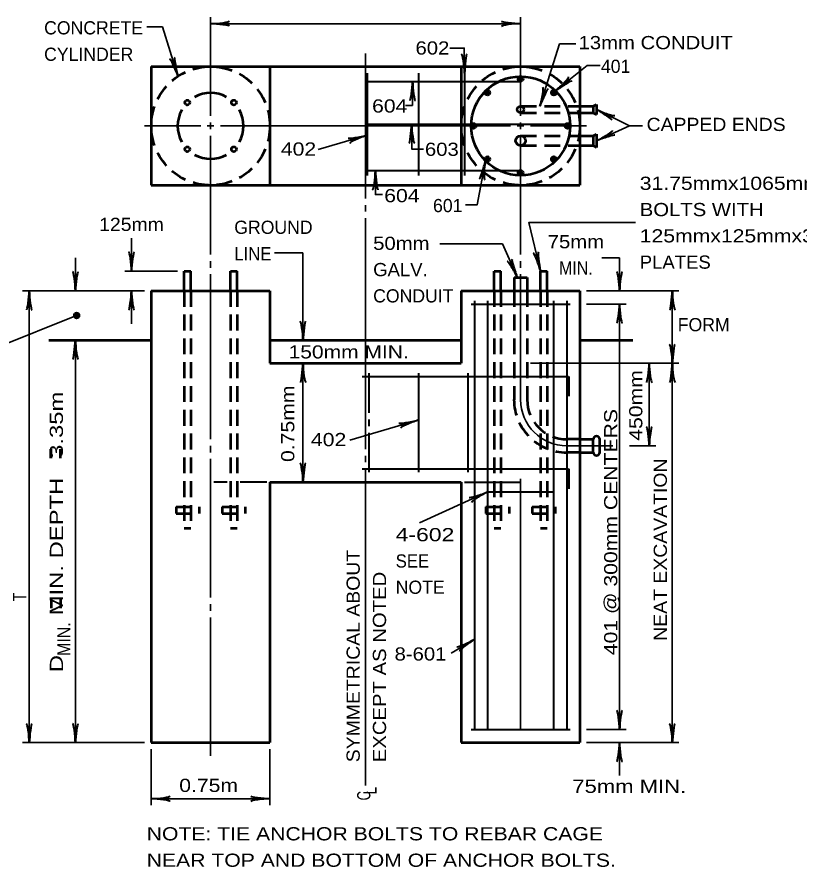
# Model space of a CAD drawing. Extents: x -29 to 827, y -14 to 530.
# Drawn here: x 196.8 to 340.2, y 180.4 to 336.3 of the extents above; entities that cross this region are included whole.
import ezdxf
from ezdxf.enums import TextEntityAlignment as Align

# ---------------------------------------------------------------- set-up
doc = ezdxf.new("R2010")
doc.units = 0
doc.header["$LTSCALE"] = 0.97
doc.linetypes.add('MEDIUM_DASHED', pattern=[4.5, 3, -1.5])
doc.layers.add('1', color=7, linetype='Continuous', lineweight=53)

msp = doc.modelspace()

# ---------------------------------------------------------------- hatches: boundary and pattern name
at = {"layer": '1'}
for points in [[(289.6196, 324.9621, 1), (288.7124, 324.9621, 1)], [(283.5254, 322.4377, 1), (282.6182, 322.4377, 1)], [(295.7138, 322.4378, 1), (294.8066, 322.4378, 1)], [(281.0012, 316.3437, 1), (280.094, 316.3437, 1)], [(298.238, 316.3437, 1), (297.3308, 316.3437, 1)], [(283.5253, 310.2494, 1), (282.6181, 310.2494, 1)], [(295.7139, 310.2496, 1), (294.8067, 310.2496, 1)], [(289.6196, 307.7253, 1), (288.7124, 307.7253, 1)], [(208.2861, 281.5657, 1), (207.1982, 281.5657, 1)]]:
    msp.add_hatch(color=256, dxfattribs=at).paths.add_polyline_path(points)

# ---------------------------------------------------------------- linework, layer by layer
at = {"layer": '1', "lineweight": 35}
for p, q in [((232.3076, 335.0878), (289.1636, 335.0878)), ((260.7476, 329.6398), (260.7476, 303.0478)), ((269.3636, 324.4798), (269.3636, 320.1118)), ((269.3636, 320.1118), (268.0676, 320.1118)), ((232.3076, 316.9438), (232.3076, 315.7438)), ((289.1636, 316.9438), (289.1636, 315.7438)), ((231.7076, 316.3438), (232.9076, 316.3438)), ((234.1316, 316.3438), (238.3556, 316.3438)), ((288.5636, 316.3438), (289.7636, 316.3438)), ((309.1316, 316.3438), (311.5316, 316.3438)), ((252.0116, 311.9998), (261.0356, 314.6158)), ((260.7476, 301.8238), (260.7476, 300.6238)), ((260.7476, 299.3998), (260.7476, 257.0638)), ((217.7876, 289.7278), (217.7876, 295.7758)), ((244.0436, 293.0638), (249.2516, 293.0638)), ((249.2516, 277.0318), (249.2516, 293.0638)), ((207.5156, 286.1038), (207.5156, 292.1518)), ((232.3076, 291.5518), (232.3076, 290.3278)), ((289.1636, 291.5518), (289.1636, 290.3278)), ((307.3076, 292.1518), (304.0436, 292.1518)), ((307.3076, 286.1038), (307.3076, 292.1518)), ((226.2596, 289.7278), (216.5876, 289.7278)), ((232.3076, 289.1278), (232.3076, 258.8878)), ((289.1636, 289.1278), (289.1636, 266.1358)), ((220.2116, 286.1038), (197.8436, 286.1038)), ((199.0436, 286.1038), (199.0436, 203.2558)), ((217.7876, 286.1038), (217.7876, 280.0558)), ((301.2596, 286.1038), (318.2036, 286.1038)), ((301.2596, 283.6798), (308.5076, 283.6798)), ((307.3076, 283.6798), (307.3076, 205.6558)), ((207.7316, 281.5678), (190.0196, 274.4878)), ((207.5156, 277.0318), (207.5156, 203.2558)), ((249.2516, 272.8078), (249.2516, 251.0158)), ((290.9876, 272.8078), (318.2036, 272.8078)), ((312.7556, 257.6878), (312.7556, 272.8078)), ((257.8196, 258.7198), (270.3236, 262.3678)), ((232.3076, 257.6878), (232.3076, 256.4638)), ((297.6356, 257.6878), (300.0596, 257.6878)), ((300.0596, 257.6878), (306.1076, 257.6878)), ((309.1316, 257.6878), (313.9556, 257.6878)), ((260.7476, 255.8638), (260.7476, 254.6638)), ((232.3076, 255.2638), (232.3076, 229.8478)), ((260.7476, 253.4398), (260.7476, 195.3838)), ((289.1636, 251.6398), (289.1636, 205.6558)), ((283.1156, 249.2158), (270.6184, 243.5634)), ((232.3076, 228.6478), (232.3076, 227.4478)), ((232.3076, 226.2238), (232.3076, 200.8318)), ((280.6916, 222.1918), (276.4196, 219.6478)), ((301.2596, 205.6558), (308.5076, 205.6558)), ((220.2116, 203.2558), (197.8436, 203.2558)), ((301.2596, 203.2558), (318.2036, 203.2558)), ((307.3076, 203.2558), (307.3076, 197.2078)), ((221.4356, 202.0318), (221.4356, 191.7598)), ((243.2036, 202.0318), (243.2036, 191.7598)), ((221.4356, 192.9598), (243.2036, 192.9598))]:
    msp.add_line(p, q, dxfattribs=at)
at = {"layer": '1'}
for p, q in [((221.4356, 327.2398), (300.0596, 327.2398)), ((221.4356, 327.2398), (221.4356, 305.4478)), ((243.2036, 327.2398), (243.2036, 305.4478)), ((278.2676, 327.2398), (278.2676, 305.4478)), ((300.0596, 327.2398), (300.0596, 305.4478)), ((300.0596, 319.9678), (302.4596, 319.9678)), ((302.4596, 319.9678), (303.0836, 320.2798)), ((302.4596, 319.9678), (302.4596, 318.7678)), ((303.0836, 320.2798), (303.0836, 318.4558)), ((300.0596, 318.7678), (302.4596, 318.7678)), ((302.4596, 318.7678), (303.0836, 318.4558)), ((300.0596, 314.5198), (302.4596, 314.5198)), ((302.4596, 314.5198), (303.0836, 314.8318)), ((302.4596, 314.5198), (302.4596, 312.7198)), ((303.0836, 314.8318), (303.0836, 312.4078)), ((300.0596, 312.7198), (302.4596, 312.7198)), ((302.4596, 312.7198), (303.0836, 312.4078)), ((221.4356, 305.4478), (300.0596, 305.4478)), ((227.4836, 286.1038), (227.4836, 289.7278)), ((227.4836, 289.7278), (228.6836, 289.7278)), ((228.6836, 286.1038), (228.6836, 289.7278)), ((235.9316, 286.1038), (235.9316, 289.7278)), ((235.9316, 289.7278), (237.1556, 289.7278)), ((237.1556, 286.1038), (237.1556, 289.7278)), ((284.3156, 286.1038), (284.3156, 289.7278)), ((284.3156, 289.7278), (285.5396, 289.7278)), ((285.5396, 286.1038), (285.5396, 289.7278)), ((287.9636, 288.5278), (290.3636, 288.5278)), ((287.9636, 288.5278), (287.9636, 286.1038)), ((290.3636, 288.5278), (290.3636, 286.1038)), ((292.7876, 286.1038), (292.7876, 289.7278)), ((292.7876, 289.7278), (294.0116, 289.7278)), ((294.0116, 286.1038), (294.0116, 289.7278)), ((221.4356, 286.1038), (221.4356, 203.2558)), ((221.4356, 286.1038), (243.2036, 286.1038)), ((243.2036, 286.1038), (243.2036, 272.8078)), ((278.2676, 286.1038), (300.0596, 286.1038)), ((278.2676, 286.1038), (278.2676, 272.8078)), ((300.0596, 286.1038), (300.0596, 203.2558)), ((202.6676, 277.0318), (221.4356, 277.0318)), ((243.2036, 277.0318), (278.2676, 277.0318)), ((300.0596, 277.0318), (309.7316, 277.0318)), ((243.2036, 272.8078), (278.2676, 272.8078)), ((300.0596, 258.8878), (302.4596, 258.8878)), ((302.4596, 256.4638), (302.4596, 258.8878)), ((303.6836, 256.4638), (303.6836, 258.8878)), ((300.0596, 256.4638), (302.4596, 256.4638)), ((243.2036, 251.0158), (278.2676, 251.0158)), ((243.2036, 251.0158), (243.2036, 203.2558)), ((278.2676, 251.0158), (278.2676, 203.2558)), ((221.4356, 203.2558), (243.2036, 203.2558)), ((278.2676, 203.2558), (300.0596, 203.2558))]:
    msp.add_line(p, q, dxfattribs=at)
at = {"layer": '1', "lineweight": 40}
for p, q in [((261.0356, 326.0158), (261.0356, 307.2718)), ((270.4196, 326.0158), (270.4196, 307.2718)), ((278.8916, 326.0158), (278.8916, 307.2718)), ((261.0356, 324.5038), (289.1636, 324.5038)), ((261.0356, 316.6558), (298.2356, 316.6558)), ((261.0356, 308.1838), (289.1636, 308.1838)), ((280.0916, 283.6798), (298.2356, 283.6798)), ((280.6916, 284.2798), (280.6916, 205.6558)), ((283.1156, 284.2798), (283.1156, 205.6558)), ((295.2116, 284.2798), (295.2116, 205.6558)), ((297.6356, 284.2798), (297.6356, 205.6558)), ((260.1236, 270.3838), (297.9236, 270.3838)), ((261.3476, 270.9838), (261.3476, 263.7358)), ((270.4196, 270.9838), (270.4196, 252.8398)), ((279.4916, 270.9838), (279.4916, 252.8398)), ((261.3476, 262.5118), (261.3476, 261.3118)), ((261.3476, 260.0878), (261.3476, 252.8398)), ((260.1236, 253.4398), (297.9236, 253.4398)), ((235.3316, 251.0158), (232.9076, 251.0158)), ((242.6036, 251.0158), (237.7556, 251.0158)), ((278.8916, 251.0158), (289.1636, 251.0158)), ((283.1156, 249.2158), (295.2116, 249.2158)), ((280.0916, 205.6558), (298.2356, 205.6558))]:
    msp.add_line(p, q, dxfattribs=at)
at = {"layer": '1', "linetype": 'MEDIUM_DASHED'}
for p, q in [((289.1636, 319.9678), (300.0596, 319.9678)), ((289.1636, 318.7678), (300.0596, 318.7678)), ((289.1636, 314.5198), (300.0596, 314.5198)), ((289.1636, 312.7198), (300.0596, 312.7198)), ((227.4836, 286.1038), (227.4836, 242.5678)), ((228.6836, 286.1038), (228.6836, 242.5678)), ((235.9316, 286.1038), (235.9316, 242.5678)), ((237.1556, 286.1038), (237.1556, 242.5678)), ((284.3156, 286.1038), (284.3156, 242.5678)), ((285.5396, 286.1038), (285.5396, 242.5678)), ((287.9636, 286.1038), (287.9636, 266.1358)), ((290.3636, 286.1038), (290.3636, 266.1358)), ((292.7876, 286.1038), (292.7876, 242.5678)), ((294.0116, 286.1038), (294.0116, 242.5678)), ((300.0596, 258.8878), (297.6356, 258.8878)), ((300.0596, 256.4638), (297.6356, 256.4638)), ((225.9716, 246.4798), (230.1956, 246.4798)), ((225.9716, 246.4798), (225.9716, 245.2798)), ((230.1956, 246.4798), (230.1956, 245.2798)), ((234.4196, 246.4798), (238.6676, 246.4798)), ((234.4196, 246.4798), (234.4196, 245.2798)), ((238.6676, 246.4798), (238.6676, 245.2798)), ((282.8036, 246.4798), (287.0516, 246.4798)), ((282.8036, 246.4798), (282.8036, 245.2798)), ((287.0516, 246.4798), (287.0516, 245.2798)), ((291.2756, 246.4798), (295.5236, 246.4798)), ((291.2756, 246.4798), (291.2756, 245.2798)), ((295.5236, 246.4798), (295.5236, 245.2798)), ((225.9716, 245.2798), (230.1956, 245.2798)), ((234.4196, 245.2798), (238.6676, 245.2798)), ((282.8036, 245.2798), (287.0516, 245.2798)), ((291.2756, 245.2798), (295.5236, 245.2798)), ((227.4836, 242.5678), (228.6836, 242.5678)), ((235.9316, 242.5678), (237.1556, 242.5678)), ((284.3156, 242.5678), (285.5396, 242.5678)), ((292.7876, 242.5678), (294.0116, 242.5678))]:
    msp.add_line(p, q, dxfattribs=at)
at = {"layer": '1', "lineweight": 60}
for p, q in [((297.9236, 270.3838), (297.9236, 266.7598)), ((297.9236, 253.4398), (297.9236, 249.8158))]:
    msp.add_line(p, q, dxfattribs=at)
at = {"layer": '1', "lineweight": 35}
for points in [[(232.3076, 318.1678), (232.3076, 322.3918), (232.3076, 336.3118)], [(289.1636, 318.1678), (289.1636, 325.4158), (289.1636, 336.3118)], [(226.3316, 325.4398), (223.4756, 334.4878), (220.6196, 334.4878)], [(278.8916, 326.0158), (278.8436, 330.5998), (276.1796, 330.5998)], [(292.7156, 319.9678), (296.3156, 331.3678), (299.2676, 331.3678)], [(295.5716, 322.7758), (301.4036, 327.4318), (303.7556, 327.4318)], [(303.0836, 319.3678), (309.1316, 316.3438), (303.0836, 313.6318)], [(269.1956, 316.6558), (269.1956, 312.0958), (271.3316, 312.0958)], [(230.5076, 316.3438), (226.2596, 316.3438), (220.2116, 316.3438)], [(238.3556, 316.3438), (280.0916, 316.3438), (287.3396, 316.3438)], [(290.9876, 316.3438), (298.2356, 316.3438), (301.2596, 316.3438)], [(232.3076, 314.5198), (232.3076, 310.2958), (232.3076, 292.7518)], [(289.1636, 314.5198), (289.1636, 307.2718), (289.1636, 292.7518)], [(282.7076, 309.9598), (281.2196, 301.8958), (279.0356, 301.8958)], [(262.5476, 308.1118), (262.5476, 303.7438), (263.8196, 303.7438)], [(292.7876, 289.7278), (290.6516, 298.6078), (310.2563, 298.6078)], [(288.5876, 288.5278), (285.8183, 294.7246), (274.3769, 294.7246)], [(316.9796, 286.1038), (316.9796, 272.8078), (316.9796, 203.2558)]]:
    msp.add_lwpolyline(points, dxfattribs=at)
at = {"layer": '1', "linetype": 'MEDIUM_DASHED'}
for centre in [(232.3148, 316.3437), (289.166, 316.3437)]:
    msp.add_circle(centre, 10.8864, dxfattribs=at)
at = {"layer": '1'}
for centre, radius in [((289.166, 316.3437), 9.072), ((289.166, 324.9621), 0.4536), ((283.0718, 322.4377), 0.4536), ((295.2602, 322.4378), 0.4536), ((228.0383, 320.6202), 0.4536), ((236.5913, 320.6202), 0.4536), ((289.166, 319.3677), 0.6048), ((280.5476, 316.3437), 0.4536), ((297.7844, 316.3437), 0.4536), ((289.166, 313.6221), 0.9072), ((228.0383, 312.0671), 0.4536), ((236.5913, 312.0671), 0.4536), ((283.0717, 310.2494), 0.4536), ((295.2603, 310.2496), 0.4536), ((289.166, 307.7253), 0.4536)]:
    msp.add_circle(centre, radius, dxfattribs=at)
at = {"layer": '1', "lineweight": 35}
msp.add_circle((207.7422, 281.5657), 0.5439, dxfattribs=at)
at = {"layer": '1'}
for centre, radius, start, end in [((232.3148, 316.3437), 6.048, 60.95954, 119.04116), ((232.3148, 316.3437), 6.048, 150.96024, 209.04046), ((232.3148, 316.3437), 6.048, 330.95884, 29.04046), ((232.3148, 316.3437), 6.048, 240.95954, 299.03976), ((303.0764, 258.8514), 0.6059, 3.43671, 176.56329), ((303.0764, 256.5048), 0.6059, 183.43671, 356.56329)]:
    msp.add_arc(centre, radius, start, end, dxfattribs=at)
at = {"layer": '1', "linetype": 'MEDIUM_DASHED'}
for radius in [9.6768, 7.2576]:
    msp.add_arc((297.6332, 266.1453), radius, 180, 270, dxfattribs=at)
at = {"layer": '1', "lineweight": 35}
msp.add_arc((297.6332, 266.1453), 8.4672, 180, 270, dxfattribs=at)
at = {"layer": '1', "lineweight": 40}
for centre, major_axis, ratio, start_param, end_param in [((233.6347, 335.4267), (-2.16, -0.1889), 0.122415, 0.89635335, 3.14159265), ((233.6347, 335.4267), (-2.16, -0.1889), 0.122415, 0.89635335, 3.14159265), ((287.8106, 335.3484), (2.1246, -0.2125), 0.07063, 3.14071475, 5.41810995), ((233.6702, 334.8365), (-2.1246, 0.2125), 0.07063, 3.14071475, 5.41810995), ((233.6702, 334.8365), (-2.1246, 0.2125), 0.07063, 3.14071475, 5.41810995), ((287.8461, 334.7583), (2.16, 0.1889), 0.122415, 0.89635335, 3.14159265), ((226.1648, 326.8051), (0.4341, -2.0906), 0.07063, 3.14071475, 5.41810995), ((278.5356, 327.3366), (0.2127, -2.1578), 0.122415, 0.89635335, 3.14159265), ((279.1253, 327.3786), (-0.189, -2.1268), 0.07063, 3.14071475, 5.41810995), ((225.6124, 326.5944), (0.8276, -2.0041), 0.122415, 0.89635335, 3.14159265), ((269.1022, 323.1255), (0.2125, 2.1246), 0.07063, 3.14071475, 5.41810995), ((269.6924, 323.1609), (-0.1889, 2.16), 0.122415, 0.89635335, 3.14159265), ((296.3888, 323.8583), (-1.57, -1.4954), 0.122415, 0.89635335, 3.14159265), ((296.7847, 323.4192), (1.7928, 1.1597), 0.07063, 6.28230741, 8.55970261), ((292.7964, 321.3318), (-0.4694, -2.1168), 0.122415, 0.89635335, 3.14159265), ((293.3699, 321.1881), (0.8415, 1.9624), 0.07063, 6.28230741, 8.55970261), ((304.1742, 318.5326), (-1.8053, 1.1402), 0.07063, 3.14071475, 5.41810995), ((304.1742, 318.5326), (-1.8053, 1.1402), 0.07063, 3.14071475, 5.41810995), ((304.4064, 319.0763), (-2.0164, 0.797), 0.122415, 0.89635335, 3.14159265), ((304.4064, 319.0763), (-2.0164, 0.797), 0.122415, 0.89635335, 3.14159265), ((268.9407, 315.2907), (0.2125, 2.1246), 0.07063, 3.14071475, 5.41810995), ((269.5308, 315.3262), (-0.1889, 2.16), 0.122415, 0.89635335, 3.14159265), ((304.1429, 314.4685), (-1.8922, -1.0586), 0.122415, 0.89635335, 3.14159265), ((259.6698, 314.486), (-2.0996, -0.3885), 0.07063, 6.28230741, 8.55970261), ((259.8685, 313.9291), (2.0216, 0.7838), 0.122415, 0.89635335, 3.14159265), ((304.4174, 313.9449), (-2.0247, -0.6781), 0.07063, 3.14071475, 5.41810995), ((282.2179, 308.6774), (-0.5967, -2.0501), 0.07063, 6.28230741, 8.55970261), ((282.8046, 308.6045), (0.2086, 2.1582), 0.122415, 0.89635335, 3.14159265), ((262.2019, 306.7823), (0.1889, 2.16), 0.122415, 3.14159265, 5.38683196), ((262.7921, 306.7468), (-0.2125, 2.1246), 0.07063, 0.86507535, 3.14247055), ((217.4654, 291.0524), (0.1889, -2.16), 0.122415, 0.89635335, 3.14159265), ((218.0555, 291.0878), (-0.2125, -2.1246), 0.07063, 3.14071475, 5.41810995), ((292.7247, 291.11), (0.2933, -2.115), 0.07063, 3.14071475, 5.41810995), ((287.7374, 289.5923), (1.052, -1.8959), 0.122415, 0.89635335, 3.14159265), ((288.262, 289.865), (0.671, -2.027), 0.07063, 3.14071475, 5.41810995), ((292.1594, 290.9367), (0.6917, -2.0549), 0.122415, 0.89635335, 3.14159265), ((207.1838, 287.4236), (0.1889, -2.16), 0.122415, 0.89635335, 3.14159265), ((207.7739, 287.459), (-0.2125, -2.1246), 0.07063, 3.14071475, 5.41810995), ((306.9758, 287.4236), (0.1889, -2.16), 0.122415, 0.89635335, 3.14159265), ((307.5659, 287.459), (-0.2125, -2.1246), 0.07063, 3.14071475, 5.41810995), ((198.7948, 284.7483), (0.2125, 2.1246), 0.07063, 3.14071475, 5.41810995), ((198.7948, 284.7483), (0.2125, 2.1246), 0.07063, 3.14071475, 5.41810995), ((199.385, 284.7838), (-0.1889, 2.16), 0.122415, 0.89635335, 3.14159265), ((199.385, 284.7838), (-0.1889, 2.16), 0.122415, 0.89635335, 3.14159265), ((217.5436, 284.7483), (0.2125, 2.1246), 0.07063, 3.14071475, 5.41810995), ((218.1338, 284.7838), (-0.1889, 2.16), 0.122415, 0.89635335, 3.14159265), ((316.7308, 284.7483), (0.2125, 2.1246), 0.07063, 3.14071475, 5.41810995), ((316.7308, 284.7483), (0.2125, 2.1246), 0.07063, 3.14071475, 5.41810995), ((317.321, 284.7838), (-0.1889, 2.16), 0.122415, 0.89635335, 3.14159265), ((317.321, 284.7838), (-0.1889, 2.16), 0.122415, 0.89635335, 3.14159265), ((307.054, 282.3291), (0.2125, 2.1246), 0.07063, 3.14071475, 5.41810995), ((307.6442, 282.3646), (-0.1889, 2.16), 0.122415, 0.89635335, 3.14159265), ((248.915, 278.3516), (0.1889, -2.16), 0.122415, 0.89635335, 3.14159265), ((249.5051, 278.387), (-0.2125, -2.1246), 0.07063, 3.14071475, 5.41810995), ((207.262, 275.6763), (0.2125, 2.1246), 0.07063, 3.14071475, 5.41810995), ((207.8522, 275.7118), (-0.1889, 2.16), 0.122415, 0.89635335, 3.14159265), ((316.6526, 274.118), (0.1889, -2.16), 0.122415, 0.89635335, 3.14159265), ((316.6526, 274.118), (0.1889, -2.16), 0.122415, 0.89635335, 3.14159265), ((317.2427, 274.1534), (-0.2125, -2.1246), 0.07063, 3.14071475, 5.41810995), ((317.2427, 274.1534), (-0.2125, -2.1246), 0.07063, 3.14071475, 5.41810995), ((248.9932, 271.4427), (0.2125, 2.1246), 0.07063, 3.14071475, 5.41810995), ((248.9932, 271.4427), (0.2125, 2.1246), 0.07063, 3.14071475, 5.41810995), ((249.5834, 271.4782), (-0.1889, 2.16), 0.122415, 0.89635335, 3.14159265), ((249.5834, 271.4782), (-0.1889, 2.16), 0.122415, 0.89635335, 3.14159265), ((312.4972, 271.4427), (0.2125, 2.1246), 0.07063, 3.14071475, 5.41810995), ((312.4972, 271.4427), (0.2125, 2.1246), 0.07063, 3.14071475, 5.41810995), ((313.0874, 271.4782), (-0.1889, 2.16), 0.122415, 0.89635335, 3.14159265), ((313.0874, 271.4782), (-0.1889, 2.16), 0.122415, 0.89635335, 3.14159265), ((316.7308, 271.4427), (0.2125, 2.1246), 0.07063, 3.14071475, 5.41810995), ((316.7308, 271.4427), (0.2125, 2.1246), 0.07063, 3.14071475, 5.41810995), ((317.321, 271.4782), (-0.1889, 2.16), 0.122415, 0.89635335, 3.14159265), ((317.321, 271.4782), (-0.1889, 2.16), 0.122415, 0.89635335, 3.14159265), ((268.9571, 262.2283), (-2.0996, -0.3885), 0.07063, 6.28230741, 8.55970261), ((269.1558, 261.6715), (2.0216, 0.7838), 0.122415, 0.89635335, 3.14159265), ((312.419, 258.998), (0.1889, -2.16), 0.122415, 0.89635335, 3.14159265), ((312.419, 258.998), (0.1889, -2.16), 0.122415, 0.89635335, 3.14159265), ((313.0091, 259.0334), (-0.2125, -2.1246), 0.07063, 3.14071475, 5.41810995), ((313.0091, 259.0334), (-0.2125, -2.1246), 0.07063, 3.14071475, 5.41810995), ((248.915, 252.3452), (0.1889, -2.16), 0.122415, 0.89635335, 3.14159265), ((249.5051, 252.3806), (-0.2125, -2.1246), 0.07063, 3.14071475, 5.41810995), ((281.7775, 248.8858), (-2.0235, -0.6816), 0.07063, 6.28230741, 8.55970261), ((282.0529, 248.3626), (1.8904, 1.0619), 0.122415, 0.89635335, 3.14159265), ((279.402, 221.7119), (1.9367, 0.8991), 0.07063, 3.14071475, 5.41810995), ((279.7331, 221.2221), (1.7627, 1.2625), 0.122415, 0.89635335, 3.14159265), ((306.9758, 206.9852), (0.1889, -2.16), 0.122415, 0.89635335, 3.14159265), ((306.9758, 206.9852), (0.1889, -2.16), 0.122415, 0.89635335, 3.14159265), ((307.5659, 207.0206), (-0.2125, -2.1246), 0.07063, 3.14071475, 5.41810995), ((307.5659, 207.0206), (-0.2125, -2.1246), 0.07063, 3.14071475, 5.41810995), ((198.7166, 204.566), (0.1889, -2.16), 0.122415, 0.89635335, 3.14159265), ((199.3067, 204.6014), (-0.2125, -2.1246), 0.07063, 3.14071475, 5.41810995), ((207.1838, 204.566), (0.1889, -2.16), 0.122415, 0.89635335, 3.14159265), ((207.7739, 204.6014), (-0.2125, -2.1246), 0.07063, 3.14071475, 5.41810995), ((316.6526, 204.566), (0.1889, -2.16), 0.122415, 0.89635335, 3.14159265), ((316.6526, 204.566), (0.1889, -2.16), 0.122415, 0.89635335, 3.14159265), ((317.2427, 204.6014), (-0.2125, -2.1246), 0.07063, 3.14071475, 5.41810995), ((317.2427, 204.6014), (-0.2125, -2.1246), 0.07063, 3.14071475, 5.41810995), ((307.054, 201.8907), (0.2125, 2.1246), 0.07063, 3.14071475, 5.41810995), ((307.6442, 201.9262), (-0.1889, 2.16), 0.122415, 0.89635335, 3.14159265), ((222.7483, 193.2987), (-2.16, -0.1889), 0.122415, 0.89635335, 3.14159265), ((222.7483, 193.2987), (-2.16, -0.1889), 0.122415, 0.89635335, 3.14159265), ((241.8458, 193.2204), (2.1246, -0.2125), 0.07063, 3.14071475, 5.41810995), ((222.7838, 192.7085), (-2.1246, 0.2125), 0.07063, 3.14071475, 5.41810995), ((222.7838, 192.7085), (-2.1246, 0.2125), 0.07063, 3.14071475, 5.41810995), ((241.8813, 192.6303), (2.16, 0.1889), 0.122415, 0.89635335, 3.14159265)]:
    msp.add_ellipse(centre, major_axis=major_axis, ratio=ratio, start_param=start_param, end_param=end_param, dxfattribs=at)

# ---------------------------------------------------------------- texts
at = {"layer": '1'}
for s, p in [('CONCRETE', (201.7796, 333.1198)), ('CYLINDER', (201.7796, 328.2718)), ('401', (303.8996, 326.0638)), ('601', (273.1076, 300.5278)), ('GROUND', (236.6516, 296.5438)), ('CONDUIT', (262.1262, 283.9678)), ('FORM', (317.9876, 278.6878)), ('NOTE', (266.2568, 230.5393))]:
    msp.add_text(s, height=2.419, dxfattribs=at).set_placement(p)
for s, height, width, p in [('13mm CONDUIT', 2.419, 1.15, (299.7956, 330.4078)), ('602', 2.419, 1.15, (269.8916, 329.4238)), ('604', 2.419, 1.2, (261.9236, 318.7918)), ('CAPPED ENDS', 2.419, 1.1, (312.2756, 315.4078)), ('402', 2.419, 1.2, (245.1956, 310.8958)), ('603', 2.419, 1.15, (271.6196, 310.8478)), ('31.75mmx1065mm ANCHOR', 2.419, 1.2, (311.0187, 304.6126)), ('604', 2.419, 1.2, (264.1556, 302.3518)), ('BOLTS WITH', 2.419, 1.15, (311.0187, 299.7934)), ('125mm', 2.419, 1.1, (211.8705, 297.0766)), ('125mmx125mmx38mm BOTTOM', 2.419, 1.2, (311.0187, 294.9742)), ('50mm', 2.419, 1.15, (262.1262, 293.6062)), ('LINE', 2.419, 0.95, (236.6516, 291.6958)), ('PLATES', 2.419, 1.05, (311.0187, 290.155)), ('GALV.', 2.419, 1.05, (262.1262, 288.787)), ('150mm MIN.', 2.4, 1.2, (246.6143, 273.6995)), ('402', 2.419, 1.2, (250.7156, 257.6158)), ('4-602', 2.419, 1.3, (266.2568, 240.1777)), ('SEE', 2.419, 0.95, (266.2568, 235.3585)), ('8-601', 2.419, 1.15, (266.0516, 218.3038)), ('0.75m', 2.419, 1.2, (226.5576, 194.2078)), ('75mm MIN.', 2.419, 1.25, (298.6492, 194.035)), ('NOTE: TIE ANCHOR BOLTS TO REBAR CAGE', 2.419, 1.2, (220.5903, 185.3295)), ('NEAR TOP AND BOTTOM OF ANCHOR BOLTS.', 2.419, 1.2, (220.5903, 180.4815))]:
    msp.add_text(s, height=height, dxfattribs=dict(at, width=width)).set_placement(p)
for s, width, p in [('75mm', 1.15, (299.3094, 293.9038)), ('MIN.', 0.9, (299.3094, 289.0846))]:
    msp.add_text(s, height=2.419, dxfattribs=dict(at, width=width)).set_placement(p, align=Align.CENTER)
for s, height, width, p in [('450mm', 2.419, 1.2, (311.4985, 258.6098)), ('0.75mm', 2.419, 1.2, (247.6697, 254.7122)), ('D      MIN. DEPTH   3.35m', 2.419, 1.35, (205.2356, 216.1678)), ('401 @ 300mm CENTERS', 2.419, 1.2, (306.9043, 219.2878)), ('=', 4.8, 0.55, (206.1758, 255.237)), ('NEAT EXCAVATION', 2.419, 1.1, (315.9956, 221.9278)), ('SYMMETRICAL ABOUT', 2.419, 1.1, (259.6676, 199.6558)), ('EXCEPT AS NOTED', 2.419, 1.15, (264.4916, 199.6558)), ('T', 2.419, 0.8, (198.4916, 229.1758)), ('=', 4.8, 0.55, (206.2548, 227.7318)), ('MIN.', 2.419, 0.9, (206.6036, 219.1678)), ('L', 2.419, 0.75, (262.7396, 193.7758)), ('C', 2.419, 0.75, (261.6116, 192.6478))]:
    msp.add_text(s, height=height, rotation=90, dxfattribs=dict(at, width=width)).set_placement(p)

doc.saveas('drawing.dxf')
